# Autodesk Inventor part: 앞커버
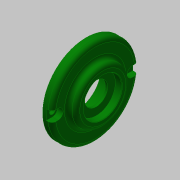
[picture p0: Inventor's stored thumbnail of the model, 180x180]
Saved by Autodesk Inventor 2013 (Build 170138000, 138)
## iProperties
Created: 2019-06
Part Number: 앞커버
Material: 알루미늄 6061
Document SubType Name: Modeling
Designer: mduedu
Density: 2.71 g/cm^3
Mass: 83.0122 g
Surface Area: 113.274 cm^2
Volume: 30.6318 cm^3
Author: mduedu
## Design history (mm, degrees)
sketch "스케치1"
  geometry: L1 (0, 0)-(7, 0); L2 (7, 0)-(7, 25); L3 (7, 25)-(0, 25); L4 (0, 25)-(0, 0); L5 (7, 0)-(14, 0); L6 (14, 0)-(14, 34); L7 (14, 34)-(7, 34); L8 (7, 34)-(7, 0); L9 (14, 0)-(20, 0); L10 (20, 0)-(20, 21); L11 (20, 21)-(14, 21); L12 (14, 21)-(14, 0)
  constraints: 24 end point, 6 parallel, 3 horizontal, 3 perpendicular
  dimensions: "d0" = 20 distance between parallel lines of L10 L4; "d2" = 7 distance of L2.end L3.end; "d3" = 7 distance of L6.end L7.end; "d4" = 50 diameter of L3 L1; "d5" = 68 diameter of L7 L5; "d6" = 42 diameter of L11 L9
revolve "회전1" sketch "스케치1" stored, may be unused: angle "d7" = 90 deg
sketch "스케치2"
  geometry: L1 (0, -25)-(0, 25) reference; L2 (0, 25)-(7, 25) reference; L3 (7, 25)-(7, 34) reference; L4 (7, 34)-(14, 34) reference; L5 (14, 34)-(14, 21) reference; L6 (14, 21)-(20, 21) reference; L7 (20, 21)-(20, -21) reference; L8 (20, -21)-(14, -21) reference; L9 (14, -21)-(14, -34) reference; L10 (14, -34)-(7, -34) reference; L11 (7, -34)-(7, -25) reference; L12 (7, -25)-(0, -25) reference; L13 (10, 0)-(10, 17.5); L14 (10, 17.5)-(0, 17.5); L15 (0, 17.5)-(0, 0); L16 (13, 0)-(13, 15); L17 (13, 15)-(10, 15); L18 (10, 15)-(10, 0); L19 (14.8, 0)-(14.8, 9); L20 (14.8, 9)-(13, 9); L21 (13, 9)-(13, 0); L22 (20, 0)-(20, 15); L23 (20, 15)-(14.8, 15); L24 (14.8, 15)-(14.8, 0)
  constraints: 24 end point, 4 horizontal, 4 horizontal alignment, 4 parallel, 4 vertical, 1 point on line, 8 other
  dimensions: "d8" = 35 dimension on L14; "d10" = 30 dimension on L17; "d11" = 18 dimension on L20; "d12" = 30 dimension on L23; "d13" = 10 distance of L13.end L14.end; "d14" = 3 distance of L16.end L17.end; "d15" = 5.2 distance of L22.end L23.end
revolve "회전2" sketch "스케치2" stored, may be unused: angle "d16" = 90 deg
chamfer "모따기1" distance "d18" = 0.5; stored, may be unused: second distance "d19" = 2, angle "d20" = 30 deg
fillet "모깎기2" dims "d21" = 0.3
fillet "모깎기3" dims "d22" = 3
chamfer "모따기2" distance "d23" = 1; stored, may be unused: second distance "d24" = 2, angle "d25" = 30 deg
fillet "모깎기4" dims "d26" = 3
sketch "스케치3" dims "d27" = 58
  geometry: L1 (-4, 29)-(-4, 33.764); L2 (4, 33.764)-(4, 29); A1 r 4 centre (0, 29) between (-4, 29) and (4, 29); A2 r 34 centre (0, 0) between (4, 33.764) and (-4, 33.764); A3 r 34 centre (0, 0) between (4, 33.764) and (-4, 33.764) reference; 3 further points
  constraints: 6 point on circle, 4 end point, 3 coincident, 2 centre point, 2 tangent, 2 vertical, 2 vertical alignment, 1 concentric, 2 other
  dimensions: "d28" = 8 diameter of A1
extrude "돌출1" cut sketch "스케치3" distance "d29" = 4.4; taper "d30" = 0 deg
sketch "스케치4"
  geometry: A1 r 4 centre (0, 29) between (-4, 29) and (4, 29) reference; 2 further points
  constraints: 1 coincident
hole "구멍1" sketch "스케치4" at (0, 29) diameter "d34" = 4.5; stored, may be unused: countersink angle "d38" = 90 deg, drill point angle "d40" = 118 deg; dims "d35" = 6, "d36" = 4, "d37" = 2, "d39" = 8
node "솔리드1"
pattern_circular "원형 패턴1" dims angle "d32" = 360 deg
pattern_circular "원형 패턴2" dims angle "d42" = 360 deg
node "절단 모서리 투영1"
